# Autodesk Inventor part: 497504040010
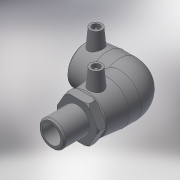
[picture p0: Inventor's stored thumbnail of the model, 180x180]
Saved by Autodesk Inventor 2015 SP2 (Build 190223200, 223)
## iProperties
Created: 2017-06
Part Number: 497504040010
Material: Generic
Description: PE Male Transition Elbow 90° 40x 1
Document SubType Name: Modeling
Designer: KIM
Mass: 224.994 g
Surface Area: 537.228 cm^2
Volume: 224.994 cm^3
Density: 1 g/cm^3
Appearance: Default
Author: KIM
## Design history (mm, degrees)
derived "497504.ipt"
feature "Solid1::497504.ipt"
feature "Solid2::497504.ipt"
tag "TaggingFeature1"
workplane "Work Plane2"
body "Solid1"
body "Solid2"
other parameters: "d2" = 55, "d4" = 28.33333, "d5" = 49.5, "d8" = 168 deg, "d10" = 17.6, "d11" = 5.86667, "d29" = 47, "d30" = 15, "d31" = 44.2, "d34" = 5 deg, "d41" = 4, "d42" = 14, "d43" = 0, "d48" = 57.5, "d50" = 4, "d51" = 17.6, "d52" = 44, "d54" = 90 deg, "d86" = 3, "d87" = 0, "d93" = 0.1, "d94" = 11, "d95" = 33.249, "d96" = 23.2743, "d98" = 44, "d99" = 55, "d100" = 39.6, "d102" = 2, "d106" = 0, "d108" = 39.6, "d114" = 44, "d115" = 0, "d116" = -44, "L_" = 129, "L_1" = 44, "A_" = 47, "d_2" = 12, "L_2" = 44, "D_1" = 55, "R_" = 33.249
